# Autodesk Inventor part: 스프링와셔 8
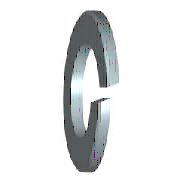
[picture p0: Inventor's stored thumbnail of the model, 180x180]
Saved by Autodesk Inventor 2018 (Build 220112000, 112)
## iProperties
IsCustomPart: 1
Created: 2012-02
Part Number: 스프링와셔 8
Material: 강철, 연강
Description: 스프링 잠금 와셔
Document SubType Name: Modeling
Standard: KS B 1324
Designer: mduedu
Standards Organization: KS
Language: ko-KR
Size Designation: 번호 3 - 8
Categories: <MemberInstance><Categories><Category DisplayName="조임쇠" InternalName="e4da775c-781d-43d5-af7c-5136215cf5a6" Mnemonic="FSTN"><Category DisplayName="와셔" InternalN
Density: 1 g/cm^3
Appearance: 파란색 - 벽 페인트 - 광택
Author: mduedu
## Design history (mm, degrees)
sketch "스케치1"
  geometry: C1 r 7.4 at (0, 0); C2 r 4.1 at (0, 0); 1 further point
  constraints: 2 centre point, 2 coincident
  dimensions: "d0" = 8.2 diameter of C2 (= SD1); "d1" = 14.8 diameter of C1 (= SD2)
extrude "본체" new body sketch "스케치1" distance "d2" = 2.5 (= SD); taper "d3" = 0 deg
sketch "스케치2"
  geometry: L1 (0, -4.1)-(0, 4.1) reference; L2 (2.5, 7.4)-(2.5, -7.4) reference; L3 (-1.2, 0)-(7.2, 0) reference; L4 (0, -0.5)-(2.5, 0.41); L5 (0, 0.5)-(2.5, 1.41)
  constraints: 4 end point, 4 point on line, 1 parallel
  dimensions: "d4" = 0.5 distance from line of L3 L4.start (= 0.2 x SD); "d5" = 0.5 distance from line of L3 L5.start (= 0.2 x SD); "d6" = 70 deg angle of L2 L4 (= FAWI)
extrude "절단부" cut sketch "스케치2" stored distance "d7" = 2.5 (= SD); taper "d8" = 0 deg
workaxis "Work Axis1"
workplane "Work Plane1"
body "Solid1"
other parameters: "SD1" = 8.2 [user parameter; used in 1 equation term], "SD2" = 14.8 [user parameter; used in 1 equation term], "SD" = 2.5 [user parameter; used in 4 equation terms], "FAWI" = 70 deg [user parameter; used in 1 equation term], "d9" = 0, "d10" = 0, "d11" = 0, "d12" = 0, "SDI" = 3.3 [user parameter], "NND" = 8 [user parameter]
